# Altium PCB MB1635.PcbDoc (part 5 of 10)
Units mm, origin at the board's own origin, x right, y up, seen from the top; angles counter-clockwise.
Board outline 127 x 97 mm, 6 copper layers (Top Layer, Signal Layer 1, Signal Layer 2, Signal Layer 3, Signal Layer 4, Bottom Layer), stack 1.557 mm thick; 593 components, 478 nets, 2435 pads, 1743 vias.
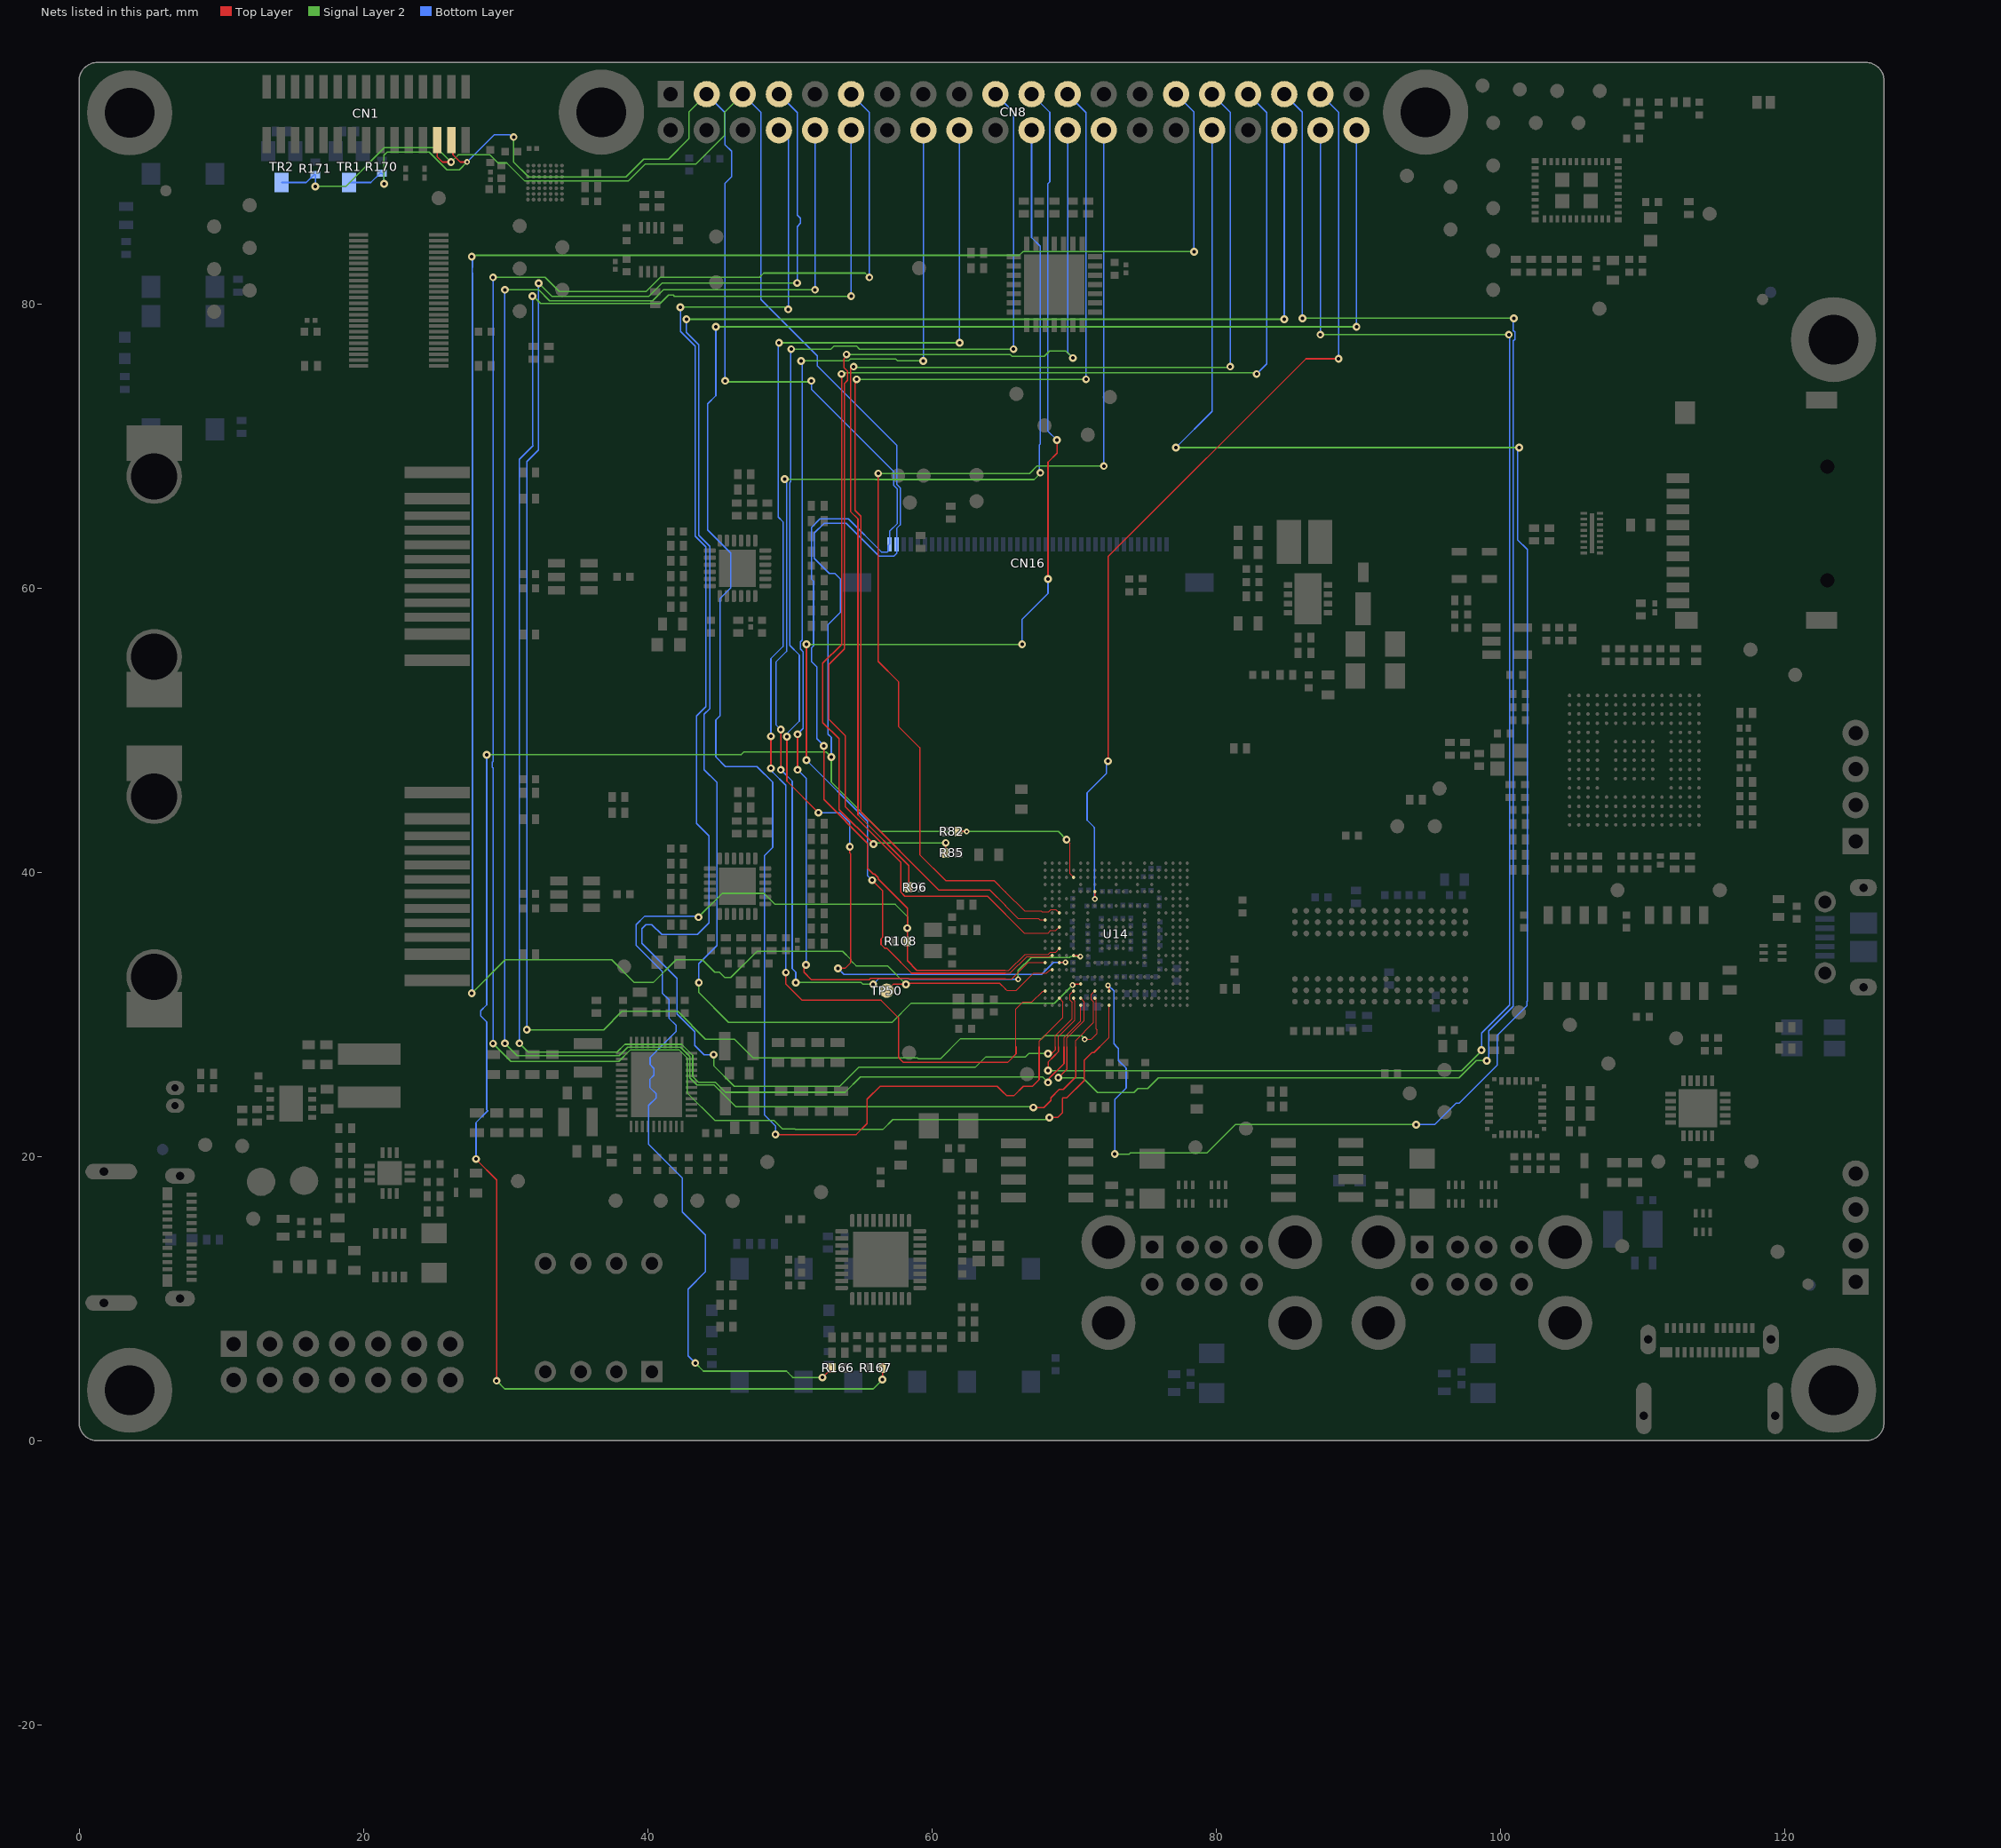
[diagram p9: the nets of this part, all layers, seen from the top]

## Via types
v1: diameter 0.55, hole 0.25, Top Layer to Bottom Layer, 1438 vias
v2: diameter 0.4, hole 0.2, Top Layer to Bottom Layer, 276 vias
v3: diameter 0.26, hole 0.1, Top Layer to Signal Layer 1, tented both sides, 29 vias

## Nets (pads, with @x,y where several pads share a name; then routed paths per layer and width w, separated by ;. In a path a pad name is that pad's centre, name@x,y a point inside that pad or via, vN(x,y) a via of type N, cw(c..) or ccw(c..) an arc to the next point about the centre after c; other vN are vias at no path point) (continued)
EXP_GPIO2: CN1.14 CN8.3 CN16.40 R108.1 R166.1 R170.2 TR1.3 U14.N3 | length 199.3
  Top Layer w0.075: 65.175,33.1 65.425,33.1 66.56,34.235 68.196,34.235 68.358,34.397 68.722,34.397 U14.N3@68.975,34.65
  Top Layer w0.09: v1(52.4,48.9) 52.4,45.125 55.475,42.05 55.475,40.275 55.88,39.87 55.974,39.87 56.22,39.624 56.22,39.53 58.275,37.475 R108.1@58.275,35.15 58.275,33.775 58.95,33.1 65.175,33.1
  Top Layer w0.1: CN1.14@26.2,91.525 26.304,91.421 26.304,90.509 26.825,89.987 27.287,89.987 v2(27.294,89.994) ; v1(52.3,4.45) R166.1@52.975,5.125
  Signal Layer 2 w0.1: v1(21.45,88.45) 21.45,90.475 21.675,90.7 24.625,90.7 25.875,89.45 26.75,89.45 v2(27.294,89.994) ; v1(30.573,91.75) 30.573,89.997 31.63,88.94 38.47,88.94 39.73,90.2 ; 39.95,90.2 39.73,90.2 ; v1(43.35,5.475) 43.925,4.9 49.775,4.9 49.9,4.775 ; v1(43.575,36.85) 45.25,38.525 48.2,38.525 48.975,37.75 57.425,37.75 58.275,36.9 v1(58.275,36.075) ; CN8.3@44.16,94.77 42.9,93.51 42.9,91.625 41.475,90.2 39.73,90.2 ; v1(45.45,74.6) 45.525,74.525 51.45,74.525 v1(51.525,74.6) ; 49.901,4.775 50.15,4.526 ; 50.15,4.525 50.225,4.45 v1(52.3,4.45)
  Bottom Layer w0.09: 51.9,51.5 51.9,49.4 v1(52.4,48.9)
  Bottom Layer w0.1: TR1.3@19,88.55 20.525,88.55 21.175,89.2 R170.2@21.3,89.2 21.45,89.05 v1(21.45,88.45) ; v2(27.294,89.994) 29.2,91.9 30.302,91.9 30.452,91.75 v1(30.573,91.75) ; v1(43.35,5.475) 42.85,5.975 42.85,10.675 44.075,11.9 44.075,14.475 42.45,16.1 42.45,18.5 40.075,20.875 40.075,23.6 40.6,24.125 40.6,24.425 40.15,24.875 40.15,25.425 40.45,25.725 40.45,26.2 40.175,26.475 40.175,26.976 42,28.801 42,29.242 41.525,29.717 41.5,29.742 41.5,31.045 41.027,31.518 41.027,33.039 39.2,34.866 39.2,36.325 39.8,36.925 43.45,36.925 v1@43.475,36.95 ; CN8.3@44.16,94.77 45.45,93.48 45.45,91.214 45.914,90.75 45.914,88.957 45.45,88.493 v1(45.45,74.6) ; v1(51.525,74.6) 51.525,74 57.325,68.2 57.325,67.23 57.575,66.98 57.575,64.56 57.025,64.01 CN16.40@57.025,63.1 56.925,63 56.925,62.609 56.866,62.55 56.45,62.55 54.125,64.875 52.137,64.875 51.525,64.263 51.525,60.648 51.675,60.498 51.675,55.937 51.525,55.787 51.525,54.85 51.9,54.475 51.9,51.5
EXP_GPIO3: CN1.13 CN8.5 CN16.39 R82.1 R167.1 R171.2 TR2.3 U14.C5 | length 224.9
  Top Layer w0.075: v1(69.475,42.3) 69.721,42.054 69.721,39.904 U14.C5@69.975,39.65
  Top Layer w0.1: CN1.13@25.2,91.525 25.2,90.362 25.412,90.15 25.575,89.987 v1(26.163,89.987) ; v1(27.925,19.825) 27.925,19.811 29.375,18.361 v1(29.375,4.225) ; v1(56.525,4.3) R167.1@56.525,5.125 ; R82.1@61.875,42.875 v2(62.45,42.875)
  Signal Layer 2 w0.09: 65.175,42.875 68.9,42.875 v1(69.475,42.3)
  Signal Layer 2 w0.1: v1(16.625,88.275) 18.75,88.275 21.48,91.005 25.145,91.005 v1(26.163,89.987) 26.671,90.496 28.907,90.496 29.477,89.925 30.085,89.925 31.36,88.65 38.63,88.65 39.83,89.85 43.4,89.85 45.4,91.85 45.4,93.47 CN8.5@46.7,94.77 ; v1(28.676,48.277) 46.573,48.277 46.575,48.275 46.775,48.475 52.575,48.475 v1(52.925,48.125) 52.925,46.35 56.4,42.875 v2(62.45,42.875) 65.175,42.875 ; v1(29.375,4.225) 29.95,3.65 55.875,3.65 v1(56.525,4.3)
  Bottom Layer w0.1: TR2.3@14.25,88.55 15.98,88.55 16.53,89.1 R171.2@16.625,89.1 v1(16.625,88.275) ; v1(27.925,19.825) 27.925,22.35 27.9,22.375 28.75,23.225 28.676,23.299 28.676,29.475 28.251,29.9 28.251,30.252 28.676,30.677 v1(28.676,48.277) ; CN8.5@46.7,94.77 47.975,93.495 47.975,80.325 51.95,76.35 51.95,75.65 57.525,70.075 57.525,67.313 57.775,67.063 57.775,64.46 57.525,64.21 CN16.39@57.525,63.1 57.525,62.451 57.336,62.262 56.288,62.262 53.975,64.575 52.425,64.575 51.725,63.875 51.725,62.106 52.787,61.044 53.181,61.044 53.575,60.65 53.575,58.3 52.7,57.425 52.7,49.725 52.925,49.5 v1(52.925,48.125)
EXP_GPIO4: CN8.7 U14.Y8 | length 131.5
  Top Layer w0.075: v2(70.75,28.25) 71.225,28.25 71.632,28.657 71.632,28.918 71.559,28.991 71.559,31.029 71.475,31.113 U14.Y8@71.475,31.15
  Signal Layer 2 w0.09: v1(31.5,28.925) 36.9,28.925 38.2,30.225 42.125,30.225 44.079,28.271 46.104,28.271 46.125,28.25 ; 41.023,81.475 v1(50.525,81.475) ; 62.375,28.3 67.715,28.3 67.929,28.514 70.536,28.514 70.775,28.275 v2@70.775,28.25
  Signal Layer 2 w0.1: v1(32.326,81.454) 32.351,81.454 33.28,80.525 40.073,80.525 41.023,81.475 ; 46.125,28.25 47.425,26.95 58.974,26.95 59.049,26.875 60.6,26.875 62.025,28.3 62.375,28.3
  Bottom Layer w0.09: v1(31.5,28.925) 31.5,68.9 32.33,69.73 32.326,69.734 v1(32.326,81.454) ; CN8.7@49.24,94.77 50.525,93.485 50.525,86.25 50.747,86.028 50.747,85.68 50.525,85.458 v1(50.525,81.475)
EXP_GPIO5: CN8.29 TP50.1 U14.T2 | length 162.3
  Top Layer w0.075: 65.175,31.8 65.275,31.7 65.947,31.7 67.151,32.904 67.466,32.904 68.077,32.904 68.3,33.127 68.452,33.127 U14.T2@68.475,33.15
  Top Layer w0.1: TP50.1@56.825,31.675 57.275,32.125 v1(58.175,32.125) 58.25,32.2 64.775,32.2 65.175,31.8
  Signal Layer 2 w0.1: v1(27.625,31.5) 29.975,33.85 37.475,33.85 39.075,32.25 40.4,32.25 42,33.85 43.851,33.85 44.726,32.975 45.05,32.975 45.25,32.775 ; v1(27.625,83.325) 27.711,83.411 27.895,83.411 27.909,83.425 66.15,83.425 66.425,83.7 78.425,83.7 v1(78.45,83.675) ; 45.251,32.775 45.426,32.6 45.851,32.6 47.701,34.45 53.72,34.45 54.3,33.87 54.3,33.799 54.674,33.425 56.875,33.425 56.95,33.35 ; 56.95,33.349 v1(58.175,32.125)
  Bottom Layer w0.1: v1(27.625,31.5) 27.675,31.55 27.675,82.179 27.651,82.203 27.651,82.555 27.675,82.579 27.675,83.275 v1(27.625,83.325) ; CN8.29@77.18,94.77 78.45,93.5 v1(78.45,83.675)
EXP_GPIO6: CN8.31 R96.2 | length 85
  Top Layer w0.1: v1(54.5,75.6) 54.35,75.6 54.275,75.525 54.275,65.4 54.8,64.875 54.8,44.05 58.375,40.475 R96.2@58.375,38.95
  Signal Layer 2 w0.1: v1(54.5,75.6) 54.45,75.6 54.4,75.55 80.95,75.55 v1(81,75.6)
  Bottom Layer w0.1: CN8.31@79.72,94.77 81,93.49 v1(81,75.6)
EXP_GPIO7: CN8.26 U14.H3 | length 79.4
  Top Layer w0.075: 65.175,38.625 66.524,37.276 67.699,37.276 67.741,37.235 68.211,37.235 68.373,37.397 68.728,37.397 U14.H3@68.975,37.15
  Top Layer w0.1: v1(56.225,68.075) 56.225,54.85 57.65,53.425 57.65,50.275 59.15,48.775 59.15,41.25 60.975,39.425 64.375,39.425 65.175,38.625
  Signal Layer 2 w0.1: v1(56.225,68.075) 66.875,68.075 67.4,68.6 v1(72.1,68.6)
  Bottom Layer w0.1: v1(72.1,68.6) CN8.26@72.1,92.23
EXP_GPIO8: CN8.24 U14.K3 | length 85.7
  Top Layer w0.075: 65.175,37.075 66.515,35.735 68.185,35.735 68.354,35.904 68.729,35.904 U14.K3@68.975,36.15
  Top Layer w0.1: v1(54,76.45) 54,76.328 53.825,76.153 53.825,75.524 54.075,75.274 54.075,74.625 53.85,74.4 53.85,55.725 52.75,54.625 52.75,50.775 53.9,49.625 53.9,44.625 57.825,40.7 57.825,38.6 58.1,38.325 63.925,38.325 65.175,37.075
  Signal Layer 2 w0.1: v1(54,76.45) 65.524,76.45 65.649,76.325 67.907,76.325 68.282,76.7 69.425,76.7 v1(69.925,76.2)
  Bottom Layer w0.1: CN8.24@69.56,92.23 69.56,76.565 v1(69.925,76.2)
EXP_GPIO9: CN8.21 U14.P2 | length 92.6
  Top Layer w0.075: 65.175,32.9 65.515,32.9 66.681,34.066 68.266,34.066 68.327,34.127 68.452,34.127 U14.P2@68.475,34.15
  Top Layer w0.1: v1(51.175,47.9) v1(51.175,56.05) ; v1(55.8,39.45) 56.525,38.725 56.525,35.426 56.428,35.329 56.428,34.926 56.677,34.677 56.824,34.677 57.8,33.701 57.8,33.675 58.575,32.9 65.175,32.9 ; v1(68.175,60.65) 68.175,68.866 68.808,69.499 68.808,70.417 v1(68.8,70.425)
  Signal Layer 2 w0.1: v1(51.175,56.05) v1(66.35,56.05)
  Bottom Layer w0.1: v1(51.175,47.9) 55.475,43.6 55.475,39.775 v1(55.8,39.45) ; v1(66.35,56.05) 66.35,57.808 68.175,59.633 v1(68.175,60.65) ; CN8.21@67.02,94.77 68.3,93.49 68.3,88.595 68.15,88.445 68.15,71.075 v1(68.8,70.425)
EXP_GPIO10: CN8.19 U14.R3 | length 98.9
  Top Layer w0.09: U14.R3@68.975,33.65 68.988,33.663 69.388,33.663 v2(69.4,33.675)
  Top Layer w0.1: v1(49.8,49.55) 49.8,46.425 v1(52.025,44.2) ; v1(53.4,33.25) 53.9,33.25 54.275,33.625 54.275,41.325 54.225,41.375 v1(54.225,41.8)
  Signal Layer 2 w0.1: v1(50.1,76.825) 52.9,76.825 53.125,77.05 54.686,77.05 54.911,76.825 v1(65.75,76.825)
  Bottom Layer w0.09: 65.175,32.825 67.725,32.825 68.575,33.675 v2(69.4,33.675)
  Bottom Layer w0.1: v1(49.8,49.55) 49.8,49.775 50.675,50.65 50.675,55.3 50,55.975 50,67.424 50.075,67.499 50.075,76.8 v1(50.1,76.825) ; v1(52.025,44.2) 53.525,44.2 54.225,43.5 v1(54.225,41.8) ; v1(53.4,33.25) 53.825,32.825 65.175,32.825 ; CN8.19@64.48,94.77 65.75,93.5 v1(65.75,76.825)
EXP_GPIO11: CN8.23 U14.J1 | length 83.5
  Top Layer w0.075: 65.175,37.675 66.081,36.769 67.489,36.769 67.608,36.65 U14.J1@67.975,36.65
  Top Layer w0.1: v1(54.7,74.7) 54.614,74.614 54.614,74.43 54.6,74.416 54.6,65.475 55,65.075 55,44.25 60.5,38.75 64.1,38.75 65.175,37.675
  Signal Layer 2 w0.1: v1(54.7,74.7) v1(70.85,74.7)
  Bottom Layer w0.1: CN8.23@69.56,94.77 70.85,93.48 v1(70.85,74.7)
EXP_GPIO12: CN8.32 U14.W10 | length 134.9
  Top Layer w0.1: v2@72.4,32.05 72.438,32.05 72.465,32.077 72.465,31.66 U14.W10@72.475,31.65
  Signal Layer 2 w0.1: v1(72.875,20.175) 73.874,20.175 73.95,20.251 79.351,20.251 81.35,22.25 v1(94.075,22.25) ; v1(77.175,69.9) v1(101.325,69.9)
  Bottom Layer w0.09: v2@72.4,32.05 72.8,31.65 72.8,27.936 73.011,27.725
  Bottom Layer w0.1: v1(72.875,20.175) 72.875,24.025 73.675,24.825 73.675,26.225 73.132,26.768 73.132,27.603 73.011,27.725 ; v1(77.175,69.9) 79.72,72.445 CN8.32@79.72,92.23 ; v1(94.075,22.25) 95.375,22.25 96.875,23.75 97.1,23.75 99.775,26.425 99.775,28.525 101.875,30.625 101.875,30.908 101.9,30.933 101.9,62.725 101.225,63.4 101.225,69.616 101.239,69.63 101.239,69.814 v1(101.325,69.9)
  other v2: 72.395,32.05
EXP_GPIO13: CN8.33 R85.1 | length 90.7
  Top Layer w0.09: v1(53.65,75.075) 53.65,56.05 52.325,54.725 52.325,50.55 53.475,49.4 53.475,44.425 v1(55.9,42) ; R85.1@60.975,41.375 v1(60.975,42.075)
  Signal Layer 2 w0.09: v1(53.65,75.075) 53.725,75.15 82.775,75.15 v1(82.85,75.075) ; v1(55.9,42) 55.975,42.075 v1(60.975,42.075)
  Bottom Layer w0.09: CN8.33@82.26,94.77 83.55,93.48 83.55,75.775 v1(82.85,75.075)
EXP_GPIO14: CN8.8 U14.W5 | length 113.4
  Top Layer w0.075: 68.7,27.725 68.7,28.497 69.89,29.687 69.89,30.86 69.725,31.025 69.725,31.4 U14.W5@69.975,31.65
  Top Layer w0.1: v1(68.175,27.25) 68.275,27.25 68.35,27.175 68.7,27.525 68.7,27.725
  Signal Layer 2 w0.09: v1(42.302,79.779) 49.628,79.779 49.778,79.629 v1(49.902,79.629)
  Signal Layer 2 w0.1: v1(44.65,27.172) 44.65,26.394 46.094,24.95 53.526,24.95 54.476,25.9 54.876,26.3 63.075,26.3 63.775,27 66.565,27 66.815,27.25 v1(68.175,27.25)
  Bottom Layer w0.09: v1(42.302,79.779) 42.302,78.073 43.35,77.025 43.35,63.675 44.1,62.925 44.1,51.655 43.45,51.005 43.45,43.45 44.325,42.575 44.325,36.45 43.5,35.625 40.999,35.625 40.299,36.325 39.881,36.325 39.605,36.049 39.605,35.02 41.422,33.203 42.072,32.553 42.072,31.603 42.072,30.053 43.325,28.8 43.325,27.825 43.978,27.172 v1(44.65,27.172) ; CN8.8@49.24,92.23 49.902,91.568 v1(49.902,79.629)
EXP_GPIO15: CN8.10 U14.W8 | length 137.9
  Top Layer w0.075: 70.12,27.725 70.12,28.17 71.39,29.44 71.39,30.885 71.225,31.05 71.225,31.4 U14.W8@71.475,31.65
  Top Layer w0.1: v1(67.15,23.45) 67.875,23.45 68.375,23.95 68.375,24.139 68.962,24.726 69.245,24.726 70.12,25.601 70.12,27.725
  Signal Layer 2 w0.1: v1(29.95,27.975) 30.825,27.1 38,27.1 38.6,27.7 42.317,27.7 42.975,27.042 42.975,25.544 43.482,25.038 44.68,25.038 46.217,23.5 67.1,23.5 v1(67.15,23.45) ; v1(29.95,81) 32.33,81 33.105,80.225 40.34,80.225 41.115,81 v1(51.78,81)
  Bottom Layer w0.1: v1(29.95,27.975) v1(29.95,81) ; v1(51.78,81) CN8.10@51.78,92.23
EXP_GPIO16: CN8.36 U14.V6 | length 133.4
  Top Layer w0.09: v2(69.9,32.075) 69.948,32.123 70.448,32.123 U14.V6@70.475,32.15
  Signal Layer 2 w0.09: 65.175,30.8 68.625,30.8 v2(69.9,32.075)
  Signal Layer 2 w0.1: v1(42.725,78.925) v1(84.8,78.925) ; v1(43.6,32.25) 43.6,31.55 45.7,29.45 57.2,29.45 58.55,30.8 65.175,30.8
  Bottom Layer w0.1: v1(42.725,78.925) 42.725,78 43.6,77.125 43.6,63.725 44.375,62.95 44.375,51.525 43.975,51.125 43.975,47.234 44.875,46.334 44.875,34.85 43.6,33.575 v1(43.6,32.25) ; v1(84.8,78.925) CN8.36@84.8,92.23
EXP_GPIO17: CN8.11 U14.AA10 | length 149.3
  Top Layer w0.075: 71.809,27.725 72.475,28.391 U14.AA10@72.475,30.65
  Top Layer w0.1: v1(68.275,22.75) 68.851,22.75 69.2,23.099 69.2,24.116 69.21,24.126 69.494,24.126 70.72,25.353 70.72,26.77 71.272,27.322 71.406,27.322 71.809,27.725
  Signal Layer 2 w0.1: v1(29.125,27.95) 30.375,26.7 37.975,26.7 38.775,27.5 42.234,27.5 42.775,26.959 42.775,24.5 44.725,22.55 48.887,22.55 49.487,21.95 50.367,21.95 50.392,21.925 56.575,21.925 57.25,22.6 68.125,22.6 v1(68.275,22.75) ; v1(29.126,81.879) 32.784,81.879 33.788,80.875 39.9,80.875 40.9,81.875 47.875,81.875 48.175,82.175 55.3,82.175 v1(55.6,81.875)
  Bottom Layer w0.1: v1(29.125,27.95) 29.125,47.353 29.076,47.401 29.076,47.753 29.126,47.803 v1(29.126,81.879) ; CN8.11@54.32,94.77 55.6,93.49 v1(55.6,81.875)
EXP_GPIO18: CN8.12 U14.AA6 | length 134.5
  Top Layer w0.075: 69.3,27.725 69.3,28.38 70.475,29.555 U14.AA6@70.475,30.65
  Top Layer w0.1: v1(68.175,25.225) 68.261,25.311 68.261,25.51 69.3,26.549 69.3,27.725
  Signal Layer 2 w0.09: v1(31.901,80.554) 31.946,80.554 32.47,80.03 40.886,80.03 41.476,80.62 41.824,80.62 41.894,80.55 v1(54.32,80.55)
  Signal Layer 2 w0.1: v1(30.975,27.975) 31.6,27.35 37.85,27.35 38.4,27.9 42.4,27.9 43.175,27.125 43.175,25.627 43.565,25.238 44.763,25.238 45.475,24.525 53.9,24.525 54.975,25.6 67.8,25.6 v1(68.175,25.225)
  Bottom Layer w0.09: v1(30.975,27.975) 30.975,69.075 31.95,70.05 31.901,70.099 v1(31.901,80.554) ; v1(54.32,80.55) CN8.12@54.32,92.23
EXP_GPIO19: CN8.35 U14.Y6 | length 122.3
  Top Layer w0.075: 69.5,27.725 69.5,28.341 70.725,29.566 70.725,30.9 U14.Y6@70.475,31.15
  Top Layer w0.1: v1(68.903,25.551) 69.5,26.148 69.5,27.725
  Signal Layer 2 w0.09: v1(68.903,25.551) 70.63,25.551 71.236,24.945 71.661,24.52 74.219,24.52 74.504,24.805 74.851,24.805 75.199,24.805 75.945,25.551 78.474,25.551 91.025,25.551 97.101,25.551 98.3,26.75 v1(99.05,26.75) ; v1(86.075,78.995) v1(100.945,78.995)
  Bottom Layer w0.09: CN8.35@84.8,94.77 86.075,93.495 v1@86.075,79 ; v1(99.05,26.75) 99.05,26.874 99.175,26.999 99.175,28.85 100.9,30.575 100.9,77.4 101.02,77.52 101.02,78.024 100.9,78.144 100.9,78.95 v1(100.945,78.995)
EXP_GPIO20: CN8.38 U14.Y5 | length 115.9
  Top Layer w0.075: 68.9,27.725 68.9,28.458 70.059,29.617 70.059,30.941 69.998,31.002 69.998,31.127 U14.Y5@69.975,31.15
  Top Layer w0.1: v1(68.178,26.051) 68.178,26.652 68.6,27.074 ; 68.6,27.075 68.9,27.375 68.9,27.725
  Signal Layer 2 w0.09: v1(68.178,26.051) 77.974,26.051 97.276,26.051 98.675,27.45 v1(98.675,27.5) ; v1(87.34,77.85) v1(100.6,77.85)
  Bottom Layer w0.09: v1(87.34,77.85) CN8.38@87.34,92.23 ; v1(98.675,27.5) 98.675,28.7 100.65,30.675 100.65,77.8 v1(100.6,77.85)
EXP_GPIO21: CN8.40 U14.Y3 | length 148.8
  Top Layer w0.075: 67.55,27.725 67.55,28.125 69.225,29.8 69.225,30.9 U14.Y3@68.975,31.15
  Top Layer w0.1: v1(49.002,21.551) 54.676,21.551 55.45,22.325 55.45,24.033 56.367,24.95 64.599,24.95 64.975,24.574 65.249,24.3 65.796,24.3 66.446,24.95 67.083,24.95 67.55,25.417 67.55,27.725
  Signal Layer 2 w0.1: v1(44.8,78.4) v1(89.88,78.4)
  Bottom Layer w0.1: v1(44.8,78.4) 44.8,73.55 44.225,72.975 44.225,64.108 45.85,62.483 45.85,60.025 45.1,59.275 45.1,51.025 44.8,50.725 44.8,48.125 45.475,47.45 47.7,47.45 48.8,46.35 48.8,41.75 48.225,41.175 48.225,22.925 49.002,22.148 v1(49.002,21.551) ; v1(89.88,78.4) CN8.40@89.88,92.23
EXP_GPIO23: CN8.16 U14.R1 | length 86.3
  Top Layer w0.075: 65.175,32.5 65.625,32.5 66.775,33.65 U14.R1@67.975,33.65
  Top Layer w0.1: v1(50.55,47.225) v1(50.55,49.725) ; v1(51.15,33.5) 51.15,33.378 51,33.228 51,32.974 51.524,32.45 55.599,32.45 55.699,32.55 58.351,32.55 58.401,32.5 65.175,32.5
  Signal Layer 2 w0.1: v1(50.8,76) 54.151,76 54.276,76.125 57.457,76.125 57.582,76 v1(59.4,76)
  Bottom Layer w0.1: v1(50.55,47.225) 51.15,46.625 v1(51.15,33.5) ; v1(50.55,49.725) 50.95,50.125 50.95,55.525 50.75,55.725 50.75,55.874 50.75,56.226 50.875,56.351 50.875,75.925 v1(50.8,76) ; v1(59.4,76) CN8.16@59.4,92.23
EXP_GPIO24: CN8.18 U14.W1 | length 99.8
  Top Layer w0.075: 65.925,27.725 65.925,30.4 66.4,30.875 67.039,30.875 67.809,31.645 67.97,31.645 U14.W1@67.975,31.65
  Top Layer w0.1: v1(48.675,47.325) v1(48.675,49.575) ; v1(49.725,32.95) 49.725,32.15 50.875,31 56.425,31 57.65,29.775 57.65,26.975 58,26.625 65.325,26.625 65.925,27.225 65.925,27.725
  Signal Layer 2 w0.1: v1(49.25,77.275) v1(61.95,77.275)
  Bottom Layer w0.1: v1(48.675,47.325) 48.675,47.203 48.801,47.078 48.801,47.049 49.725,46.125 v1(49.725,32.95) ; v1(48.675,49.575) 48.675,55.05 49.525,55.9 49.525,64.675 49.2,65 49.2,77.225 v1(49.25,77.275) ; v1@61.94,77.275 CN8.18@61.94,92.23
EXP_GPIO25: CN8.22 U14.P5 | length 100.8
  Top Layer w0.09: U14.P5@69.975,34.15 70.002,34.123 70.406,34.123 v2(70.45,34.079)
  Top Layer w0.1: v1(49.375,47.225) v1(49.375,50.05)
  Signal Layer 2 w0.09: v2(66.075,32.475) 66.075,33.1 66.991,34.016 69.701,34.016 69.764,34.079 v2(70.45,34.079)
  Signal Layer 2 w0.1: v1(49.65,67.675) 56.024,67.675 56.049,67.65 67.2,67.65 67.628,68.078 v1(67.628,68.128) ; v1(50.425,32.25) 55.042,32.25 55.167,32.125 v1(55.875,32.125)
  Bottom Layer w0.09: 65.175,32.475 v2(66.075,32.475)
  Bottom Layer w0.1: v1(49.375,47.225) 50.175,46.425 50.175,33.225 50.425,32.975 v1(50.425,32.25) ; v1(49.375,50.05) 49.025,50.4 49.025,54.8 49.775,55.55 49.775,67.428 49.65,67.553 v1(49.65,67.675) ; v1(55.875,32.125) 56.3,32.55 58.351,32.55 58.426,32.475 65.175,32.475 ; CN8.22@67.02,92.23 67.02,84.68 67.625,84.075 67.625,70.151 67.575,70.101 67.575,68.181 v1(67.628,68.128)
EXP_GPIO26: CN8.37 U14.E8 | length 66.6
  Top Layer w0.09: v2(71.475,38.125) U14.E8@71.475,38.65
  Top Layer w0.1: v1(72.4,47.825) 72.4,62.225 86.325,76.15 v1(88.625,76.15)
  Bottom Layer w0.09: 71.425,43.125 71.425,38.175 v2(71.475,38.125)
  Bottom Layer w0.1: 71.425,43.125 71.425,43.175 70.925,43.675 70.925,45.6 72.275,46.95 72.275,47.578 72.4,47.703 v1(72.4,47.825) ; CN8.37@87.34,94.77 88.625,93.485 v1(88.625,76.15)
